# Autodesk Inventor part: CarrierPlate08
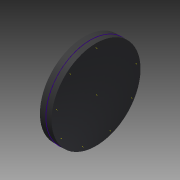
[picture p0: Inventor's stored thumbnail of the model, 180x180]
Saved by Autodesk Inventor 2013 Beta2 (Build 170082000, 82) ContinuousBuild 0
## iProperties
Created: 2008-02
Part Number: CarrierPlate08
Document SubType Name: Modeling
Designer: grh
Density: 1 g/cm^3
Material: Generic
Author: grh
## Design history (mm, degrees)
sketch "Sketch1"
  geometry: L1 (48.514, 0)-(0, 0); L2 (0, 0)-(37.164, 31.184); L3 (8.424, 47.777)-(0, 0); L4 (-24.257, 42.014)-(0, 0); L5 (-45.588, 16.593)-(0, 0); L6 (-45.588, -16.593)-(0, 0); L7 (-24.257, -42.014)-(0, 0); L8 (8.424, -47.777)-(0, 0); C1 r 53.34 at (0, 0)
  constraints: 16 end point, 7 equal length, 1 centre point, 1 horizontal, 1 other
  dimensions: "BlankDiameter" = 106.68 diameter of C1; "PlanetRadius" = 48.514 distance of L1.start L1.end; "Angle1" = 40 deg angle of L2 L1; "Angle2" = 40 deg angle of L3 L2; "Angle3" = 40 deg angle of L4 L3; "Angle4" = 40 deg angle of L5 L4; "Angle5" = 40 deg angle of L6 L5; "Angle7" = 40 deg angle of L7 L6; "Angle8" = 40 deg angle of L7 L8
extrude "Extrusion1" new body sketch "Sketch1" stored distance "d9" = 13.97; taper "d10" = 0 deg
node "Axis1"
node "Axis2"
node "Axis3"
node "Axis4"
node "Axis5"
node "Axis6"
node "Axis7"
node "Axis8"
node "Axis9"
body "Solid1"
